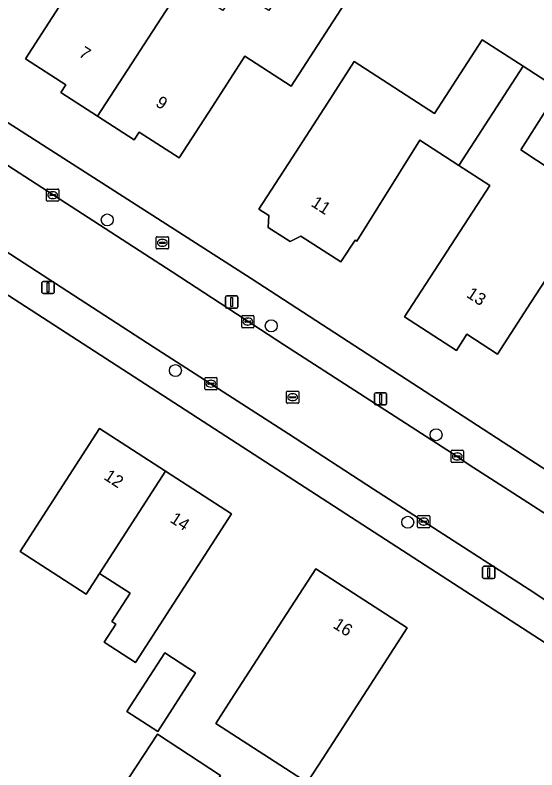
# Model space of a CAD drawing. Extents: x 161139 to 161601, y 381708 to 382245.
# Drawn here: x 161431.3 to 161473.8, y 382048.1 to 382109.7 of the extents above; entities that cross this region are included whole.
import ezdxf

# ---------------------------------------------------------------- set-up
doc = ezdxf.new("R2010")
doc.units = 0
for name, color, linetype in [('IMGEO_Boom', 7, 'Continuous'), ('IMGEO_Brandkraan', 7, 'Continuous'), ('IMGEO_Erf', 7, 'Continuous'), ('IMGEO_Kolk', 7, 'Continuous'), ('IMGEO_Lichtmast', 7, 'Continuous'), ('IMGEO_Pand', 7, 'Continuous'), ('IMGEO_Pand_nummerreeks', 7, 'Continuous'), ('IMGEO_Rijbaan_lokaal_open', 7, 'Continuous'), ('IMGEO_Rioolput', 7, 'Continuous'), ('IMGEO_Voetpad_open', 7, 'Continuous')]:
    doc.layers.add(name, color=color, linetype=linetype)

msp = doc.modelspace()

# ---------------------------------------------------------------- linework, layer by layer
at = {"layer": 'IMGEO_Boom'}
for centre in [(161438.771, 382092.992), (161452.147, 382084.355), (161444.324, 382080.707), (161465.598, 382075.473), (161463.28, 382068.331)]:
    msp.add_circle(centre, 0.489, dxfattribs=at)
at = {"layer": 'IMGEO_Brandkraan'}
for p, q in [((161442.766, 382090.701), (161442.766, 382091.553)), ((161442.841, 382091.627), (161443.693, 382091.627)), ((161443.025, 382091.121), (161443.025, 382091.133)), ((161443.068, 382091.17), (161443.466, 382091.17)), ((161443.254, 382091.407), (161443.279, 382091.407)), ((161443.509, 382091.133), (161443.509, 382091.121)), ((161443.767, 382091.553), (161443.767, 382090.701)), ((161443.693, 382090.627), (161442.841, 382090.627)), ((161443.463, 382091.084), (161443.065, 382091.084)), ((161443.277, 382090.847), (161443.252, 382090.847))]:
    msp.add_line(p, q, dxfattribs=at)
for points in [[(161442.766, 382090.701), (161442.766, 382091.553)], [(161442.841, 382091.627), (161443.693, 382091.627)], [(161443.767, 382091.553), (161443.767, 382090.701)], [(161443.693, 382090.627), (161442.841, 382090.627)]]:
    msp.add_lwpolyline(points, dxfattribs=at)
for centre, radius, start, end in [((161442.843, 382091.551), 0.0765, 91.55205, 178.44795), ((161442.843, 382091.551), 0.0765, 91.55205, 178.44795), ((161443.065, 382091.13), 0.0403, 85.87752, 175.75265), ((161443.062, 382091.12), 0.0366, 178.93798, 274.71019), ((161443.466, 382091.127), 0.043, 264.86636, 352.45326), ((161443.47, 382091.132), 0.0386, 1.73085, 96.63898), ((161443.691, 382091.551), 0.0765, 1.55205, 88.44795), ((161443.691, 382091.551), 0.0765, 1.55205, 88.44795), ((161442.843, 382090.703), 0.0765, 181.55205, 268.44795), ((161442.843, 382090.703), 0.0765, 181.55205, 268.44795), ((161443.691, 382090.703), 0.0765, 271.55205, 358.44795), ((161443.691, 382090.703), 0.0765, 271.55205, 358.44795)]:
    msp.add_arc(centre, radius, start, end, dxfattribs=at)
for centre, major_axis, ratio, start_param, end_param in [((161443.253, 382091.127), (-0.387, 0.002), 0.722429, 4.712389, 7.853982), ((161443.278, 382091.127), (-0.39, 0.002), 0.717154, 1.570796, 4.712389)]:
    msp.add_ellipse(centre, major_axis=major_axis, ratio=ratio, start_param=start_param, end_param=end_param, dxfattribs=at)
at = {"layer": 'IMGEO_Erf'}
for points in [[(161553.295, 382144.911), (161544.61, 382147.101), (161500, 382158.072), (161477.956, 382163.494), (161457.897, 382168.303), (161418.52, 382178.097), (161389.844, 382185.251), (161387.058, 382185.651), (161384.186, 382184.996), (161381.949, 382183.375), (161380.259, 382181.034), (161377.586, 382172.934), (161374.321, 382163.969), (161372.26, 382158.835), (161369.98, 382153.637), (161365.084, 382143.565), (161365.175, 382143.293), (161389.855, 382127.317), (161408.789, 382114.947), (161450.498, 382088.211), (161500, 382056.07), (161523.437, 382040.853), (161561.628, 382099.383), (161581.409, 382129.761)], [(161320.525, 382089.631), (161313.623, 382083.997), (161443.483, 382000), (161462.38, 381987.777), (161470.3, 382000), (161498.24, 382043.117), (161359.011, 382133.266)], [(161459.379, 382112.577), (161453.77, 382103.907), (161450.002, 382106.345), (161447.354, 382102.252), (161444.638, 382098.054), (161441.366, 382100.171), (161440.952, 382099.531), (161437.966, 382101.463), (161434.978, 382103.397), (161435.385, 382104.027), (161432.104, 382106.149), (161434.82, 382110.347)], [(161476.987, 382091.901), (161473.333, 382086.254), (161470.617, 382082.055), (161468.115, 382083.674), (161467.256, 382082.346), (161463.023, 382085.085), (161469.966, 382095.815), (161467.455, 382097.44), (161464.273, 382099.499), (161459.126, 382091.268), (161458.989, 382091.357), (161457.833, 382089.569), (161454.573, 382091.678), (161453.687, 382091.225), (161451.901, 382092.38), (161451.95, 382093.346), (161451.141, 382093.869), (161453.857, 382098.067), (161456.737, 382102.518), (161458.914, 382105.916), (161465.469, 382101.675), (161469.366, 382107.698), (161472.701, 382105.54), (161475.629, 382103.645), (161472.521, 382098.709), (161475.134, 382096.962)]]:
    msp.add_lwpolyline(points, dxfattribs=at)
for points in [[(161438.514, 382058.548), (161439.461, 382060.012), (161439.138, 382060.221), (161440.638, 382062.542), (161438.134, 382064.16), (161437.044, 382062.474), (161431.656, 382065.957), (161435.418, 382071.776), (161438.132, 382075.974), (161443.52, 382072.49), (161448.911, 382069.005), (161446.197, 382064.807), (161441.078, 382056.89)], [(161453.071, 382060.334), (161455.786, 382064.533), (161463.24, 382059.714), (161460.525, 382055.515), (161456.345, 382049.049), (161455.075, 382047.085), (161447.621, 382051.906), (161448.89, 382053.869)], [(161443.461, 382057.675), (161445.976, 382056.048), (161442.884, 382051.265), (161440.368, 382052.892)], [(161442.858, 382051.048), (161448.016, 382047.664), (161444.589, 382042.441), (161439.431, 382045.825)]]:
    msp.add_lwpolyline(points, close=True, dxfattribs=at)
at = {"layer": 'IMGEO_Kolk'}
for p, q in [((161433.819, 382094.594), (161433.819, 382095.446)), ((161433.894, 382095.52), (161434.746, 382095.52)), ((161434.82, 382095.446), (161434.82, 382094.594)), ((161434.078, 382095.014), (161434.078, 382095.026)), ((161434.516, 382094.977), (161434.118, 382094.977)), ((161434.121, 382095.063), (161434.519, 382095.063)), ((161434.307, 382095.3), (161434.332, 382095.3)), ((161434.562, 382095.026), (161434.562, 382095.014)), ((161434.746, 382094.52), (161433.894, 382094.52)), ((161434.33, 382094.74), (161434.305, 382094.74)), ((161449.735, 382084.278), (161449.735, 382085.13)), ((161449.81, 382085.204), (161450.662, 382085.204)), ((161450.223, 382084.984), (161450.248, 382084.984)), ((161450.736, 382085.13), (161450.736, 382084.278)), ((161449.994, 382084.698), (161449.994, 382084.71)), ((161450.432, 382084.661), (161450.034, 382084.661)), ((161450.037, 382084.747), (161450.435, 382084.747)), ((161450.246, 382084.424), (161450.221, 382084.424)), ((161450.478, 382084.71), (161450.478, 382084.698)), ((161450.662, 382084.204), (161449.81, 382084.204)), ((161446.721, 382079.212), (161446.721, 382080.064)), ((161446.796, 382080.138), (161447.648, 382080.138)), ((161447.722, 382080.064), (161447.722, 382079.212)), ((161446.98, 382079.632), (161446.98, 382079.644)), ((161447.418, 382079.595), (161447.02, 382079.595)), ((161447.023, 382079.681), (161447.421, 382079.681)), ((161447.209, 382079.918), (161447.234, 382079.918)), ((161447.464, 382079.644), (161447.464, 382079.632)), ((161447.648, 382079.138), (161446.796, 382079.138)), ((161447.232, 382079.358), (161447.207, 382079.358)), ((161466.823, 382073.276), (161466.823, 382074.128)), ((161466.898, 382074.202), (161467.75, 382074.202)), ((161467.311, 382073.982), (161467.336, 382073.982)), ((161467.824, 382074.128), (161467.824, 382073.276)), ((161467.082, 382073.696), (161467.082, 382073.708)), ((161467.52, 382073.659), (161467.122, 382073.659)), ((161467.125, 382073.745), (161467.523, 382073.745)), ((161467.334, 382073.422), (161467.309, 382073.422)), ((161467.566, 382073.708), (161467.566, 382073.696)), ((161467.75, 382073.202), (161466.898, 382073.202)), ((161464.08, 382067.96), (161464.08, 382068.812)), ((161464.155, 382068.886), (161465.007, 382068.886)), ((161464.339, 382068.38), (161464.339, 382068.392)), ((161464.777, 382068.343), (161464.379, 382068.343)), ((161464.382, 382068.429), (161464.78, 382068.429)), ((161464.568, 382068.666), (161464.593, 382068.666)), ((161464.823, 382068.392), (161464.823, 382068.38)), ((161465.081, 382068.812), (161465.081, 382067.96)), ((161465.007, 382067.886), (161464.155, 382067.886)), ((161464.591, 382068.106), (161464.566, 382068.106))]:
    msp.add_line(p, q, dxfattribs=at)
for points in [[(161433.819, 382094.594), (161433.819, 382095.446)], [(161433.894, 382095.52), (161434.746, 382095.52)], [(161434.82, 382095.446), (161434.82, 382094.594)], [(161434.746, 382094.52), (161433.894, 382094.52)], [(161449.735, 382084.278), (161449.735, 382085.13)], [(161449.81, 382085.204), (161450.662, 382085.204)], [(161450.736, 382085.13), (161450.736, 382084.278)], [(161450.662, 382084.204), (161449.81, 382084.204)], [(161446.721, 382079.212), (161446.721, 382080.064)], [(161446.796, 382080.138), (161447.648, 382080.138)], [(161447.722, 382080.064), (161447.722, 382079.212)], [(161447.648, 382079.138), (161446.796, 382079.138)], [(161466.823, 382073.276), (161466.823, 382074.128)], [(161466.898, 382074.202), (161467.75, 382074.202)], [(161467.824, 382074.128), (161467.824, 382073.276)], [(161467.75, 382073.202), (161466.898, 382073.202)], [(161464.08, 382067.96), (161464.08, 382068.812)], [(161464.155, 382068.886), (161465.007, 382068.886)], [(161465.081, 382068.812), (161465.081, 382067.96)], [(161465.007, 382067.886), (161464.155, 382067.886)]]:
    msp.add_lwpolyline(points, dxfattribs=at)
for centre, radius, start, end in [((161433.896, 382095.444), 0.0765, 91.55205, 178.44795), ((161433.896, 382095.444), 0.0765, 91.55205, 178.44795), ((161434.744, 382095.444), 0.0765, 1.55205, 88.44795), ((161434.744, 382095.444), 0.0765, 1.55205, 88.44795), ((161434.118, 382095.023), 0.0403, 85.87752, 175.75265), ((161434.115, 382095.013), 0.0366, 178.93798, 274.71019), ((161434.519, 382095.02), 0.043, 264.86636, 352.45326), ((161434.523, 382095.025), 0.0386, 1.73085, 96.63898), ((161433.896, 382094.596), 0.0765, 181.55205, 268.44795), ((161433.896, 382094.596), 0.0765, 181.55205, 268.44795), ((161434.744, 382094.596), 0.0765, 271.55205, 358.44795), ((161434.744, 382094.596), 0.0765, 271.55205, 358.44795), ((161449.812, 382085.128), 0.0765, 91.55205, 178.44795), ((161449.812, 382085.128), 0.0765, 91.55205, 178.44795), ((161450.66, 382085.128), 0.0765, 1.55205, 88.44795), ((161450.66, 382085.128), 0.0765, 1.55205, 88.44795), ((161450.034, 382084.707), 0.0403, 85.87752, 175.75265), ((161450.031, 382084.697), 0.0366, 178.93798, 274.71019), ((161450.435, 382084.704), 0.043, 264.86636, 352.45326), ((161450.439, 382084.709), 0.0386, 1.73085, 96.63898), ((161449.812, 382084.28), 0.0765, 181.55205, 268.44795), ((161449.812, 382084.28), 0.0765, 181.55205, 268.44795), ((161450.66, 382084.28), 0.0765, 271.55205, 358.44795), ((161450.66, 382084.28), 0.0765, 271.55205, 358.44795), ((161446.798, 382080.062), 0.0765, 91.55205, 178.44795), ((161446.798, 382080.062), 0.0765, 91.55205, 178.44795), ((161447.646, 382080.062), 0.0765, 1.55205, 88.44795), ((161447.646, 382080.062), 0.0765, 1.55205, 88.44795), ((161447.02, 382079.641), 0.0403, 85.87752, 175.75265), ((161447.017, 382079.631), 0.0366, 178.93798, 274.71019), ((161447.421, 382079.638), 0.043, 264.86636, 352.45326), ((161447.425, 382079.643), 0.0386, 1.73085, 96.63898), ((161446.798, 382079.214), 0.0765, 181.55205, 268.44795), ((161446.798, 382079.214), 0.0765, 181.55205, 268.44795), ((161447.646, 382079.214), 0.0765, 271.55205, 358.44795), ((161447.646, 382079.214), 0.0765, 271.55205, 358.44795), ((161466.9, 382074.126), 0.0765, 91.55205, 178.44795), ((161466.9, 382074.126), 0.0765, 91.55205, 178.44795), ((161467.748, 382074.126), 0.0765, 1.55205, 88.44795), ((161467.748, 382074.126), 0.0765, 1.55205, 88.44795), ((161466.9, 382073.278), 0.0765, 181.55205, 268.44795), ((161466.9, 382073.278), 0.0765, 181.55205, 268.44795), ((161467.122, 382073.705), 0.0403, 85.87752, 175.75265), ((161467.119, 382073.695), 0.0366, 178.93798, 274.71019), ((161467.523, 382073.702), 0.043, 264.86636, 352.45326), ((161467.527, 382073.707), 0.0386, 1.73085, 96.63898), ((161467.748, 382073.278), 0.0765, 271.55205, 358.44795), ((161467.748, 382073.278), 0.0765, 271.55205, 358.44795), ((161464.157, 382068.81), 0.0765, 91.55205, 178.44795), ((161464.157, 382068.81), 0.0765, 91.55205, 178.44795), ((161464.379, 382068.389), 0.0403, 85.87752, 175.75265), ((161464.376, 382068.379), 0.0366, 178.93798, 274.71019), ((161464.78, 382068.386), 0.043, 264.86636, 352.45326), ((161464.784, 382068.391), 0.0386, 1.73085, 96.63898), ((161465.005, 382068.81), 0.0765, 1.55205, 88.44795), ((161465.005, 382068.81), 0.0765, 1.55205, 88.44795), ((161464.157, 382067.962), 0.0765, 181.55205, 268.44795), ((161464.157, 382067.962), 0.0765, 181.55205, 268.44795), ((161465.005, 382067.962), 0.0765, 271.55205, 358.44795), ((161465.005, 382067.962), 0.0765, 271.55205, 358.44795)]:
    msp.add_arc(centre, radius, start, end, dxfattribs=at)
for centre, major_axis, ratio, start_param, end_param in [((161434.306, 382095.02), (-0.387, 0.002), 0.722429, 4.712389, 7.853982), ((161434.331, 382095.02), (-0.39, 0.002), 0.717154, 1.570796, 4.712389), ((161450.222, 382084.704), (-0.387, 0.002), 0.722429, 4.712389, 7.853982), ((161450.247, 382084.704), (-0.39, 0.002), 0.717154, 1.570796, 4.712389), ((161447.208, 382079.638), (-0.387, 0.002), 0.722429, 4.712389, 7.853982), ((161447.233, 382079.638), (-0.39, 0.002), 0.717154, 1.570796, 4.712389), ((161467.31, 382073.702), (-0.387, 0.002), 0.722429, 4.712389, 7.853982), ((161467.335, 382073.702), (-0.39, 0.002), 0.717154, 1.570796, 4.712389), ((161464.567, 382068.386), (-0.387, 0.002), 0.722429, 4.712389, 7.853982), ((161464.592, 382068.386), (-0.39, 0.002), 0.717154, 1.570796, 4.712389)]:
    msp.add_ellipse(centre, major_axis=major_axis, ratio=ratio, start_param=start_param, end_param=end_param, dxfattribs=at)
at = {"layer": 'IMGEO_Lichtmast'}
for p, q in [((161433.446, 382087.085), (161433.446, 382087.885)), ((161433.446, 382087.885), (161433.446, 382087.085)), ((161433.546, 382087.985), (161434.336, 382087.985)), ((161434.336, 382087.985), (161433.546, 382087.985)), ((161434.436, 382087.885), (161434.436, 382087.085)), ((161434.436, 382087.085), (161434.436, 382087.885)), ((161434.336, 382086.985), (161433.546, 382086.985)), ((161433.546, 382086.985), (161434.336, 382086.985)), ((161448.522, 382086.803), (161449.312, 382086.803)), ((161449.312, 382086.803), (161448.522, 382086.803)), ((161448.422, 382085.903), (161448.422, 382086.703)), ((161448.422, 382086.703), (161448.422, 382085.903)), ((161449.412, 382086.703), (161449.412, 382085.903)), ((161449.412, 382085.903), (161449.412, 382086.703)), ((161449.312, 382085.803), (161448.522, 382085.803)), ((161448.522, 382085.803), (161449.312, 382085.803)), ((161460.573, 382078), (161460.573, 382078.8)), ((161460.573, 382078.8), (161460.573, 382078)), ((161460.673, 382078.9), (161461.463, 382078.9)), ((161461.463, 382078.9), (161460.673, 382078.9)), ((161461.563, 382078.8), (161461.563, 382078)), ((161461.563, 382078), (161461.563, 382078.8)), ((161461.463, 382077.9), (161460.673, 382077.9)), ((161460.673, 382077.9), (161461.463, 382077.9)), ((161469.393, 382063.835), (161469.393, 382064.635)), ((161469.393, 382064.635), (161469.393, 382063.835)), ((161469.493, 382064.735), (161470.283, 382064.735)), ((161470.283, 382064.735), (161469.493, 382064.735)), ((161470.383, 382064.635), (161470.383, 382063.835)), ((161470.383, 382063.835), (161470.383, 382064.635)), ((161470.283, 382063.735), (161469.493, 382063.735)), ((161469.493, 382063.735), (161470.283, 382063.735))]:
    msp.add_line(p, q, dxfattribs=at)
for points in [[(161433.866, 382087.86), (161434.016, 382087.86), (161434.016, 382087.11), (161433.866, 382087.11), (161433.866, 382087.86)], [(161448.842, 382086.678), (161448.992, 382086.678), (161448.992, 382085.928), (161448.842, 382085.928), (161448.842, 382086.678)], [(161460.993, 382078.775), (161461.143, 382078.775), (161461.143, 382078.025), (161460.993, 382078.025), (161460.993, 382078.775)], [(161469.813, 382064.61), (161469.963, 382064.61), (161469.963, 382063.86), (161469.813, 382063.86), (161469.813, 382064.61)]]:
    msp.add_lwpolyline(points, dxfattribs=at)
for centre, start, end in [((161433.546, 382087.885), 90, 180), ((161433.546, 382087.885), 90, 180), ((161434.336, 382087.885), 0, 90), ((161434.336, 382087.885), 360, 90), ((161433.546, 382087.085), 180, 270), ((161433.546, 382087.085), 180, 270), ((161434.336, 382087.085), 270, 0), ((161434.336, 382087.085), 270, 0), ((161448.522, 382086.703), 90, 180), ((161448.522, 382086.703), 90, 180), ((161449.312, 382086.703), 0, 90), ((161449.312, 382086.703), 360, 90), ((161448.522, 382085.903), 180, 270), ((161448.522, 382085.903), 180, 270), ((161449.312, 382085.903), 270, 0), ((161449.312, 382085.903), 270, 0), ((161460.673, 382078.8), 90, 180), ((161460.673, 382078.8), 90, 180), ((161461.463, 382078.8), 0, 90), ((161461.463, 382078.8), 360, 90), ((161460.673, 382078), 180, 270), ((161460.673, 382078), 180, 270), ((161461.463, 382078), 270, 0), ((161461.463, 382078), 270, 0), ((161469.493, 382064.635), 90, 180), ((161469.493, 382064.635), 90, 180), ((161470.283, 382064.635), 0, 90), ((161470.283, 382064.635), 360, 90), ((161469.493, 382063.835), 180, 270), ((161469.493, 382063.835), 180, 270), ((161470.283, 382063.835), 270, 0), ((161470.283, 382063.835), 270, 0)]:
    msp.add_arc(centre, 0.1, start, end, dxfattribs=at)
at = {"layer": 'IMGEO_Pand'}
for points in [[(161444.922, 382112.208), (161441.455, 382114.516), (161440.486, 382115.143), (161438.679, 382116.311), (161438.514, 382116.055), (161434.82, 382110.347), (161432.104, 382106.149), (161435.385, 382104.027), (161434.978, 382103.397), (161437.966, 382101.463)], [(161450.002, 382106.345), (161453.77, 382103.907), (161459.379, 382112.577), (161455.281, 382115.234), (161451.951, 382110.085), (161449.302, 382111.799), (161448.197, 382110.09), (161444.922, 382112.208), (161437.966, 382101.463), (161440.952, 382099.531), (161441.366, 382100.171), (161444.638, 382098.054), (161447.354, 382102.252)], [(161467.455, 382097.44), (161472.701, 382105.54), (161469.366, 382107.698), (161465.469, 382101.675), (161458.914, 382105.916), (161456.737, 382102.518), (161453.857, 382098.067), (161451.141, 382093.869), (161451.95, 382093.346), (161451.901, 382092.38), (161453.687, 382091.225), (161454.573, 382091.678), (161457.833, 382089.569), (161458.989, 382091.357), (161459.126, 382091.268), (161464.273, 382099.499)], [(161479.416, 382095.655), (161480.537, 382097.387), (161476.937, 382099.717), (161475.817, 382097.985), (161475.134, 382096.962), (161472.521, 382098.709), (161475.629, 382103.645), (161472.701, 382105.54), (161467.455, 382097.44), (161469.966, 382095.815), (161463.023, 382085.085), (161467.256, 382082.346), (161468.115, 382083.674), (161470.617, 382082.055), (161473.333, 382086.254), (161476.987, 382091.901)], [(161443.52, 382072.49), (161438.132, 382075.974), (161435.418, 382071.776), (161431.656, 382065.957), (161437.044, 382062.474), (161438.134, 382064.16)], [(161446.197, 382064.807), (161448.911, 382069.005), (161443.52, 382072.49), (161438.134, 382064.16), (161440.638, 382062.542), (161439.138, 382060.221), (161439.461, 382060.012), (161438.514, 382058.548), (161441.078, 382056.89)], [(161453.071, 382060.334), (161448.89, 382053.869), (161447.621, 382051.906), (161455.075, 382047.085), (161456.345, 382049.049), (161460.525, 382055.515), (161463.24, 382059.714), (161455.786, 382064.533)], [(161442.884, 382051.265), (161445.976, 382056.048), (161443.461, 382057.675), (161440.368, 382052.892)], [(161448.016, 382047.664), (161442.858, 382051.048), (161439.431, 382045.825), (161444.589, 382042.441)]]:
    msp.add_lwpolyline(points, close=True, dxfattribs=at)
at = {"layer": 'IMGEO_Rijbaan_lokaal_open'}
for points in [[(161521.765, 382038.348), (161512.078, 382044.654), (161498.469, 382053.534), (161494.669, 382055.998), (161485.554, 382061.86), (161483.251, 382063.426), (161480.028, 382065.466), (161471.488, 382070.983), (161468.287, 382073.003), (161467.324, 382073.702), (161460.192, 382078.284), (161453.24, 382082.778), (161444.055, 382088.754), (161440.905, 382090.804), (161426.931, 382099.82), (161420.597, 382103.968), (161416.21, 382106.739), (161403.197, 382115.21)], [(161398.574, 382111.058), (161401.761, 382109.008), (161415.306, 382100.289), (161421.669, 382096.147), (161435.549, 382087.163), (161442.527, 382082.644), (161453.542, 382075.54), (161460.477, 382071.037), (161473.195, 382062.836), (161477.592, 382059.945), (161498.051, 382046.741), (161499.796, 382045.589), (161510.796, 382038.454), (161522.385, 382030.943)]]:
    msp.add_lwpolyline(points, dxfattribs=at)
at = {"layer": 'IMGEO_Rioolput'}
for p, q in [((161453.39, 382078.108), (161453.39, 382078.96)), ((161453.465, 382079.034), (161454.317, 382079.034)), ((161453.878, 382078.814), (161453.903, 382078.814)), ((161454.391, 382078.96), (161454.391, 382078.108)), ((161453.649, 382078.528), (161453.649, 382078.54)), ((161454.087, 382078.491), (161453.689, 382078.491)), ((161453.692, 382078.577), (161454.09, 382078.577)), ((161453.901, 382078.254), (161453.876, 382078.254)), ((161454.133, 382078.54), (161454.133, 382078.528)), ((161454.317, 382078.034), (161453.465, 382078.034))]:
    msp.add_line(p, q, dxfattribs=at)
for points in [[(161453.39, 382078.108), (161453.39, 382078.96)], [(161453.465, 382079.034), (161454.317, 382079.034)], [(161454.391, 382078.96), (161454.391, 382078.108)], [(161454.317, 382078.034), (161453.465, 382078.034)]]:
    msp.add_lwpolyline(points, dxfattribs=at)
for centre, radius, start, end in [((161453.467, 382078.958), 0.0765, 91.55205, 178.44795), ((161453.467, 382078.958), 0.0765, 91.55205, 178.44795), ((161454.315, 382078.958), 0.0765, 1.55205, 88.44795), ((161454.315, 382078.958), 0.0765, 1.55205, 88.44795), ((161453.689, 382078.537), 0.0403, 85.87752, 175.75265), ((161453.686, 382078.527), 0.0366, 178.93798, 274.71019), ((161454.09, 382078.534), 0.043, 264.86636, 352.45326), ((161454.094, 382078.539), 0.0386, 1.73085, 96.63898), ((161453.467, 382078.11), 0.0765, 181.55205, 268.44795), ((161453.467, 382078.11), 0.0765, 181.55205, 268.44795), ((161454.315, 382078.11), 0.0765, 271.55205, 358.44795), ((161454.315, 382078.11), 0.0765, 271.55205, 358.44795)]:
    msp.add_arc(centre, radius, start, end, dxfattribs=at)
for centre, major_axis, ratio, start_param, end_param in [((161453.877, 382078.534), (-0.387, 0.002), 0.722429, 4.712389, 7.853982), ((161453.902, 382078.534), (-0.39, 0.002), 0.717154, 1.570796, 4.712389)]:
    msp.add_ellipse(centre, major_axis=major_axis, ratio=ratio, start_param=start_param, end_param=end_param, dxfattribs=at)
at = {"layer": 'IMGEO_Voetpad_open'}
for points in [[(161421.669, 382096.147), (161415.306, 382100.289), (161401.761, 382109.008), (161398.574, 382111.058), (161389.569, 382116.981), (161386.277, 382119.018), (161382.915, 382121.211), (161379.746, 382123.279), (161360.833, 382135.554), (161359.011, 382133.266), (161498.24, 382043.117), (161500.799, 382041.385)], [(161403.197, 382115.21), (161416.21, 382106.739), (161420.597, 382103.968), (161426.931, 382099.82), (161440.905, 382090.804), (161444.055, 382088.754), (161453.24, 382082.778), (161460.192, 382078.284), (161467.324, 382073.702), (161468.287, 382073.003), (161471.488, 382070.983), (161480.028, 382065.466), (161483.251, 382063.426), (161485.554, 382061.86), (161494.669, 382055.998), (161498.469, 382053.534), (161512.078, 382044.654), (161521.765, 382038.348), (161525.596, 382035.854), (161527.949, 382034.358)], [(161450.498, 382088.211), (161408.789, 382114.947)], [(161499.883, 382045.525), (161499.84, 382045.557), (161499.796, 382045.589), (161498.051, 382046.741), (161477.592, 382059.945), (161473.195, 382062.836), (161460.477, 382071.037), (161453.542, 382075.54), (161442.527, 382082.644), (161435.549, 382087.163), (161421.669, 382096.147)], [(161528.309, 382037.772), (161526.784, 382038.653), (161525.518, 382039.495), (161523.437, 382040.853), (161500, 382056.07), (161450.498, 382088.211)]]:
    msp.add_lwpolyline(points, dxfattribs=at)

# ---------------------------------------------------------------- texts
at = {"layer": 'IMGEO_Pand_nummerreeks'}
for s, rotation, p in [('7', 327.1466, (161436.374, 382106.392)), ('9', 327.1466, (161442.641, 382102.345)), ('11', 327.27689, (161455.327, 382094.175)), ('13', 327.09503, (161468.001, 382086.749)), ('12', 327.11795, (161438.426, 382071.878)), ('14', 327.11795, (161443.818, 382068.392)), ('16', 327.11739, (161457.115, 382059.768))]:
    msp.add_text(s, height=1, rotation=rotation, dxfattribs=at).set_placement(p)

doc.saveas('drawing.dxf')
